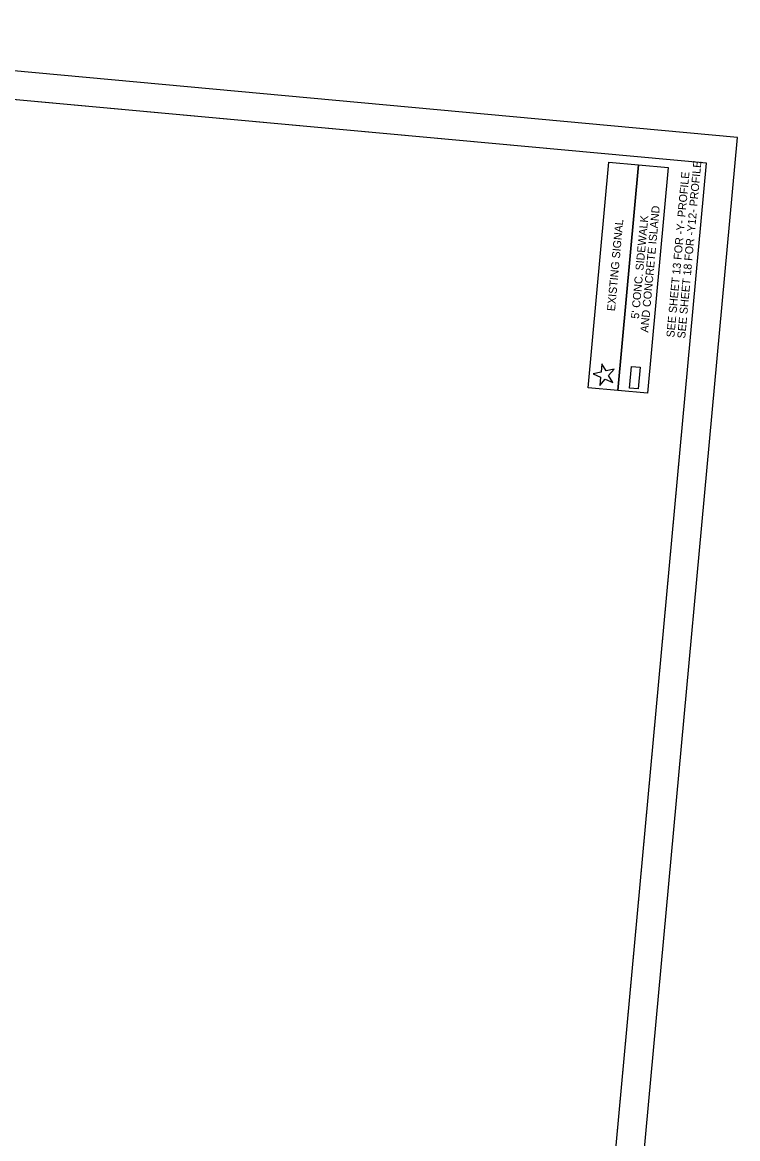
# Model space of a CAD drawing. Extents: x 2012234 to 2013485, y 445892 to 447846.
# Drawn here: x 2012860 to 2013485, y 446869 to 447846 of the extents above; entities that cross this region are included whole.
import ezdxf

# ---------------------------------------------------------------- set-up
doc = ezdxf.new("R2010")
doc.units = 0
for name, color, linetype in [('Old_Level_1', 7, 'Continuous'), ('Prop DSN Text', 7, 'Continuous'), ('Prop RDY Traffic Signal CELL', 7, 'Continuous'), ('Prop Shade Medium', 7, 'Continuous'), ('Sheet Clip Boundary CELL', 7, 'Continuous'), ('Sheet Plan And Profile CELL', 7, 'Continuous'), ('Sheet Plot Border Outside CELL', 7, 'Continuous')]:
    doc.layers.add(name, color=color, linetype=linetype)

msp = doc.modelspace()

# ---------------------------------------------------------------- linework, layer by layer
at = {"layer": 'Old_Level_1'}
for points in [[(2013354.62, 447526.24), (2013372.77, 447723.6), (2013398.72, 447721.22), (2013380.57, 447523.86)], [(2013380.57, 447523.86), (2013398.72, 447721.22), (2013424.67, 447718.83), (2013406.52, 447521.47)]]:
    msp.add_lwpolyline(points, close=True, dxfattribs=at)
at = {"layer": 'Prop RDY Traffic Signal CELL'}
msp.add_lwpolyline([(2013365.48, 447535.48), (2013364.82, 447528.31), (2013369.57, 447533.73), (2013376.21, 447530.88), (2013372.51, 447537.09), (2013377.27, 447542.51), (2013370.23, 447540.92), (2013366.54, 447547.12), (2013365.88, 447539.93), (2013358.84, 447538.34), (2013365.48, 447535.48)], dxfattribs=at)
at = {"layer": 'Prop Shade Medium'}
msp.add_lwpolyline([(2013390.77, 447525.92), (2013392.51, 447544.89), (2013400.1, 447544.19), (2013398.36, 447525.22)], close=True, dxfattribs=at)
at = {"layer": 'Sheet Clip Boundary CELL'}
msp.add_lwpolyline([(2012286.31, 446445.78), (2012511.43, 446429.21), (2012750.66, 446410.08), (2013333.05, 446362.08), (2013458.14, 447722.64), (2012593.82, 447802.11), (2012575.5, 447602.9), (2012460.65, 447613.46), (2012442.34, 447414.28), (2012375.93, 447420.39)], close=True, dxfattribs=at)
at = {"layer": 'Sheet Plan And Profile CELL'}
msp.add_lwpolyline([(2012412.56, 447818.78), (2012275.22, 446325.08), (2013320.81, 446228.94), (2013458.14, 447722.64)], close=True, dxfattribs=at)
at = {"layer": 'Sheet Plot Border Outside CELL'}
msp.add_lwpolyline([(2013329.68, 446052.39), (2013485.33, 447745.24), (2012389.95, 447845.96), (2012234.3, 446153.1)], close=True, dxfattribs=at)

# ---------------------------------------------------------------- texts
at = {"layer": 'Prop DSN Text'}
for s, p in [('SEE SHEET 18 FOR -Y12- PROFILE', (2013439.39, 447569.17)), ('SEE SHEET 13 FOR -Y- PROFILE', (2013429.9, 447570.04)), ('AND CONCRETE ISLAND', (2013407.09, 447574.38)), ('EXISTING SIGNAL', (2013378.02, 447593.02)), ("5' CONC. SIDEWALK", (2013398.98, 447586.39))]:
    msp.add_text(s, height=7, rotation=84.74666, dxfattribs=at).set_placement(p)

doc.saveas('drawing.dxf')
